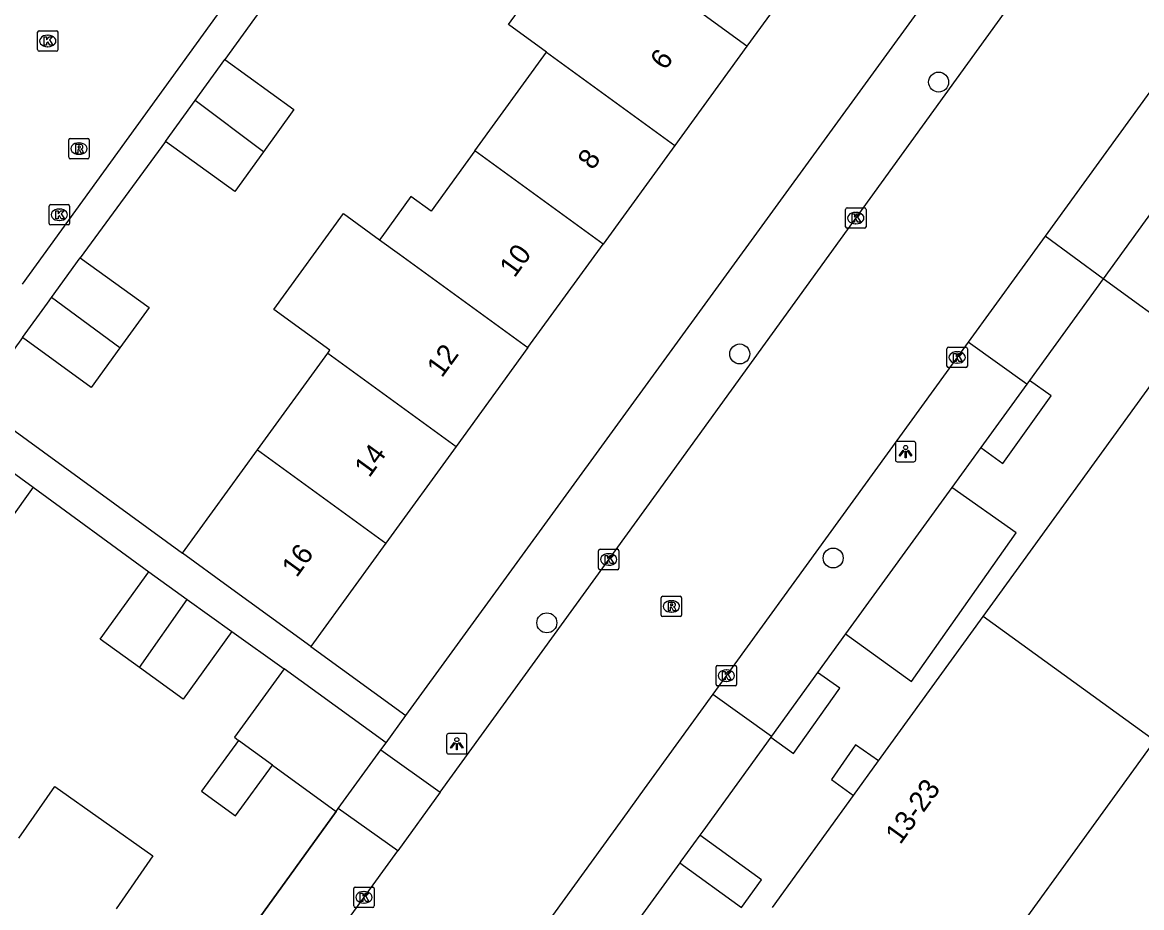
# Model space of a CAD drawing. Extents: x 159675 to 160530, y 382179 to 382901.
# Drawn here: x 160284.3 to 160339.1, y 382619.4 to 382662.7 of the extents above; entities that cross this region are included whole.
import ezdxf

# ---------------------------------------------------------------- set-up
doc = ezdxf.new("R2010")
doc.units = 0
for name, color, linetype in [('IMGEO_Boom', 7, 'Continuous'), ('IMGEO_Kolk', 7, 'Continuous'), ('IMGEO_Lichtpunt', 7, 'Continuous'), ('IMGEO_Muur', 7, 'Continuous'), ('IMGEO_Pand', 7, 'Continuous'), ('IMGEO_Pand_nummerreeks', 7, 'Continuous'), ('IMGEO_Rijbaan_lokaal_gesloten', 7, 'Continuous'), ('IMGEO_Rijbaan_lokaal_open', 7, 'Continuous'), ('IMGEO_Rioolput', 7, 'Continuous'), ('IMGEO_Voetpad_open', 7, 'Continuous')]:
    doc.layers.add(name, color=color, linetype=linetype)

msp = doc.modelspace()

# ---------------------------------------------------------------- linework, layer by layer
at = {"layer": 'IMGEO_Boom'}
for centre in [(160329.135, 382659.771), (160319.394, 382646.462), (160323.969, 382636.475), (160309.945, 382633.301)]:
    msp.add_circle(centre, 0.489, dxfattribs=at)
at = {"layer": 'IMGEO_Kolk'}
for p, q in [((160284.999, 382661.358), (160284.999, 382662.21)), ((160285.074, 382662.284), (160285.926, 382662.284)), ((160285.487, 382662.064), (160285.512, 382662.064)), ((160286, 382662.21), (160286, 382661.358)), ((160285.51, 382661.504), (160285.485, 382661.504)), ((160285.926, 382661.284), (160285.074, 382661.284)), ((160285.567, 382652.85), (160285.567, 382653.702)), ((160285.642, 382653.776), (160286.494, 382653.776)), ((160286.568, 382653.702), (160286.568, 382652.85)), ((160286.055, 382653.556), (160286.08, 382653.556)), ((160324.577, 382652.689), (160324.577, 382653.541)), ((160324.652, 382653.615), (160325.504, 382653.615)), ((160325.065, 382653.395), (160325.09, 382653.395)), ((160325.578, 382653.541), (160325.578, 382652.689)), ((160286.494, 382652.776), (160285.642, 382652.776)), ((160286.078, 382652.996), (160286.053, 382652.996)), ((160325.504, 382652.615), (160324.652, 382652.615)), ((160325.088, 382652.835), (160325.063, 382652.835)), ((160329.543, 382645.867), (160329.543, 382646.719)), ((160329.618, 382646.793), (160330.47, 382646.793)), ((160330.031, 382646.573), (160330.056, 382646.573)), ((160330.544, 382646.719), (160330.544, 382645.867)), ((160330.47, 382645.793), (160329.618, 382645.793)), ((160330.054, 382646.013), (160330.029, 382646.013)), ((160312.475, 382635.977), (160312.475, 382636.829)), ((160312.55, 382636.903), (160313.402, 382636.903)), ((160313.476, 382636.829), (160313.476, 382635.977)), ((160312.963, 382636.683), (160312.988, 382636.683)), ((160313.402, 382635.903), (160312.55, 382635.903)), ((160312.986, 382636.123), (160312.961, 382636.123)), ((160318.311, 382631.216), (160319.163, 382631.216)), ((160318.236, 382630.29), (160318.236, 382631.142)), ((160318.724, 382630.996), (160318.749, 382630.996)), ((160319.237, 382631.142), (160319.237, 382630.29)), ((160319.163, 382630.216), (160318.311, 382630.216)), ((160318.747, 382630.436), (160318.722, 382630.436)), ((160300.487, 382619.441), (160300.487, 382620.293)), ((160300.562, 382620.367), (160301.414, 382620.367)), ((160301.488, 382620.293), (160301.488, 382619.441)), ((160300.975, 382620.147), (160301, 382620.147)), ((160301.414, 382619.367), (160300.562, 382619.367)), ((160300.998, 382619.587), (160300.973, 382619.587))]:
    msp.add_line(p, q, dxfattribs=at)
for points in [[(160284.999, 382661.358), (160284.999, 382662.21)], [(160285.074, 382662.284), (160285.926, 382662.284)], [(160285.32, 382661.984), (160285.443, 382661.984), (160285.443, 382661.833), (160285.573, 382661.984), (160285.737, 382661.984), (160285.591, 382661.833), (160285.744, 382661.584), (160285.592, 382661.584), (160285.507, 382661.748), (160285.443, 382661.681), (160285.443, 382661.584), (160285.32, 382661.584), (160285.32, 382661.984)], [(160286, 382662.21), (160286, 382661.358)], [(160285.926, 382661.284), (160285.074, 382661.284)], [(160285.567, 382652.85), (160285.567, 382653.702)], [(160285.642, 382653.776), (160286.494, 382653.776)], [(160286.568, 382653.702), (160286.568, 382652.85)], [(160285.888, 382653.476), (160286.011, 382653.476), (160286.011, 382653.325), (160286.141, 382653.476), (160286.305, 382653.476), (160286.159, 382653.325), (160286.312, 382653.076), (160286.16, 382653.076), (160286.075, 382653.24), (160286.011, 382653.173), (160286.011, 382653.076), (160285.888, 382653.076), (160285.888, 382653.476)], [(160324.577, 382652.689), (160324.577, 382653.541)], [(160324.652, 382653.615), (160325.504, 382653.615)], [(160324.898, 382653.315), (160325.021, 382653.315), (160325.021, 382653.164), (160325.151, 382653.315), (160325.315, 382653.315), (160325.169, 382653.164), (160325.322, 382652.915), (160325.17, 382652.915), (160325.085, 382653.079), (160325.021, 382653.012), (160325.021, 382652.915), (160324.898, 382652.915), (160324.898, 382653.315)], [(160325.578, 382653.541), (160325.578, 382652.689)], [(160286.494, 382652.776), (160285.642, 382652.776)], [(160325.504, 382652.615), (160324.652, 382652.615)], [(160329.543, 382645.867), (160329.543, 382646.719)], [(160329.618, 382646.793), (160330.47, 382646.793)], [(160330.544, 382646.719), (160330.544, 382645.867)], [(160329.864, 382646.493), (160329.987, 382646.493), (160329.987, 382646.342), (160330.117, 382646.493), (160330.281, 382646.493), (160330.135, 382646.342), (160330.288, 382646.093), (160330.136, 382646.093), (160330.051, 382646.257), (160329.987, 382646.19), (160329.987, 382646.093), (160329.864, 382646.093), (160329.864, 382646.493)], [(160330.47, 382645.793), (160329.618, 382645.793)], [(160312.475, 382635.977), (160312.475, 382636.829)], [(160312.55, 382636.903), (160313.402, 382636.903)], [(160313.476, 382636.829), (160313.476, 382635.977)], [(160312.796, 382636.603), (160312.919, 382636.603), (160312.919, 382636.452), (160313.049, 382636.603), (160313.213, 382636.603), (160313.067, 382636.452), (160313.22, 382636.203), (160313.068, 382636.203), (160312.983, 382636.367), (160312.919, 382636.3), (160312.919, 382636.203), (160312.796, 382636.203), (160312.796, 382636.603)], [(160313.402, 382635.903), (160312.55, 382635.903)], [(160318.311, 382631.216), (160319.163, 382631.216)], [(160318.236, 382630.29), (160318.236, 382631.142)], [(160318.557, 382630.916), (160318.68, 382630.916), (160318.68, 382630.765), (160318.81, 382630.916), (160318.974, 382630.916), (160318.828, 382630.765), (160318.981, 382630.516), (160318.829, 382630.516), (160318.744, 382630.68), (160318.68, 382630.613), (160318.68, 382630.516), (160318.557, 382630.516), (160318.557, 382630.916)], [(160319.237, 382631.142), (160319.237, 382630.29)], [(160319.163, 382630.216), (160318.311, 382630.216)], [(160300.487, 382619.441), (160300.487, 382620.293)], [(160300.562, 382620.367), (160301.414, 382620.367)], [(160301.488, 382620.293), (160301.488, 382619.441)], [(160300.808, 382620.067), (160300.931, 382620.067), (160300.931, 382619.916), (160301.061, 382620.067), (160301.225, 382620.067), (160301.079, 382619.916), (160301.232, 382619.667), (160301.08, 382619.667), (160300.995, 382619.831), (160300.931, 382619.764), (160300.931, 382619.667), (160300.808, 382619.667), (160300.808, 382620.067)], [(160301.414, 382619.367), (160300.562, 382619.367)]]:
    msp.add_lwpolyline(points, dxfattribs=at)
for centre, start, end in [((160285.076, 382662.208), 91.552, 178.448), ((160285.076, 382662.208), 91.552, 178.448), ((160285.924, 382662.208), 1.552, 88.448), ((160285.924, 382662.208), 1.552, 88.448), ((160285.076, 382661.36), 181.552, 268.448), ((160285.076, 382661.36), 181.552, 268.448), ((160285.924, 382661.36), 271.552, 358.448), ((160285.924, 382661.36), 271.552, 358.448), ((160285.644, 382653.7), 91.552, 178.448), ((160285.644, 382653.7), 91.552, 178.448), ((160286.492, 382653.7), 1.552, 88.448), ((160286.492, 382653.7), 1.552, 88.448), ((160324.654, 382653.539), 91.552, 178.448), ((160324.654, 382653.539), 91.552, 178.448), ((160325.502, 382653.539), 1.552, 88.448), ((160325.502, 382653.539), 1.552, 88.448), ((160285.644, 382652.852), 181.552, 268.448), ((160285.644, 382652.852), 181.552, 268.448), ((160286.492, 382652.852), 271.552, 358.448), ((160286.492, 382652.852), 271.552, 358.448), ((160324.654, 382652.691), 181.552, 268.448), ((160324.654, 382652.691), 181.552, 268.448), ((160325.502, 382652.691), 271.552, 358.448), ((160325.502, 382652.691), 271.552, 358.448), ((160329.62, 382646.717), 91.552, 178.448), ((160329.62, 382646.717), 91.552, 178.448), ((160330.468, 382646.717), 1.552, 88.448), ((160330.468, 382646.717), 1.552, 88.448), ((160329.62, 382645.869), 181.552, 268.448), ((160329.62, 382645.869), 181.552, 268.448), ((160330.468, 382645.869), 271.552, 358.448), ((160330.468, 382645.869), 271.552, 358.448), ((160312.552, 382636.827), 91.552, 178.448), ((160312.552, 382636.827), 91.552, 178.448), ((160313.4, 382636.827), 1.552, 88.448), ((160313.4, 382636.827), 1.552, 88.448), ((160312.552, 382635.979), 181.552, 268.448), ((160312.552, 382635.979), 181.552, 268.448), ((160313.4, 382635.979), 271.552, 358.448), ((160313.4, 382635.979), 271.552, 358.448), ((160318.313, 382631.14), 91.552, 178.448), ((160318.313, 382631.14), 91.552, 178.448), ((160319.161, 382631.14), 1.552, 88.448), ((160319.161, 382631.14), 1.552, 88.448), ((160318.313, 382630.292), 181.552, 268.448), ((160318.313, 382630.292), 181.552, 268.448), ((160319.161, 382630.292), 271.552, 358.448), ((160319.161, 382630.292), 271.552, 358.448), ((160300.564, 382620.291), 91.552, 178.448), ((160300.564, 382620.291), 91.552, 178.448), ((160301.412, 382620.291), 1.552, 88.448), ((160301.412, 382620.291), 1.552, 88.448), ((160300.564, 382619.443), 181.552, 268.448), ((160300.564, 382619.443), 181.552, 268.448), ((160301.412, 382619.443), 271.552, 358.448), ((160301.412, 382619.443), 271.552, 358.448)]:
    msp.add_arc(centre, 0.0765, start, end, dxfattribs=at)
for centre, major_axis, ratio, start_param, end_param in [((160285.486, 382661.784), (-0.387, 0.002), 0.722429, 4.712389, 7.853982), ((160285.511, 382661.784), (-0.39, 0.002), 0.717154, 1.570796, 4.712389), ((160286.054, 382653.276), (-0.387, 0.002), 0.722429, 4.712389, 7.853982), ((160286.079, 382653.276), (-0.39, 0.002), 0.717154, 1.570796, 4.712389), ((160325.064, 382653.115), (-0.387, 0.002), 0.722429, 4.712389, 7.853982), ((160325.089, 382653.115), (-0.39, 0.002), 0.717154, 1.570796, 4.712389), ((160330.03, 382646.293), (-0.387, 0.002), 0.722429, 4.712389, 7.853982), ((160330.055, 382646.293), (-0.39, 0.002), 0.717154, 1.570796, 4.712389), ((160312.962, 382636.403), (-0.387, 0.002), 0.722429, 4.712389, 7.853982), ((160312.987, 382636.403), (-0.39, 0.002), 0.717154, 1.570796, 4.712389), ((160318.723, 382630.716), (-0.387, 0.002), 0.722429, 4.712389, 7.853982), ((160318.748, 382630.716), (-0.39, 0.002), 0.717154, 1.570796, 4.712389), ((160300.974, 382619.867), (-0.387, 0.002), 0.722429, 4.712389, 7.853982), ((160300.999, 382619.867), (-0.39, 0.002), 0.717154, 1.570796, 4.712389)]:
    msp.add_ellipse(centre, major_axis=major_axis, ratio=ratio, start_param=start_param, end_param=end_param, dxfattribs=at)
at = {"layer": 'IMGEO_Lichtpunt'}
for p, q in [((160327.92, 382642.181), (160327.112, 382642.181)), ((160327.92, 382642.181), (160327.112, 382642.181)), ((160327.018, 382642.086), (160327.018, 382641.279)), ((160327.018, 382642.086), (160327.018, 382641.279)), ((160328.014, 382641.279), (160328.014, 382642.086)), ((160328.014, 382641.279), (160328.014, 382642.086)), ((160327.112, 382641.185), (160327.92, 382641.185)), ((160327.112, 382641.185), (160327.92, 382641.185)), ((160305.037, 382627.787), (160305.037, 382626.98)), ((160305.037, 382627.787), (160305.037, 382626.98)), ((160305.939, 382627.882), (160305.131, 382627.882)), ((160305.939, 382627.882), (160305.131, 382627.882)), ((160306.033, 382626.98), (160306.033, 382627.787)), ((160306.033, 382626.98), (160306.033, 382627.787)), ((160305.131, 382626.886), (160305.939, 382626.886)), ((160305.131, 382626.886), (160305.939, 382626.886))]:
    msp.add_line(p, q, dxfattribs=at)
for points in [[(160327.392, 382641.75), (160327.431, 382641.722), (160327.243, 382641.46), (160327.205, 382641.487), (160327.392, 382641.75)], [(160327.494, 382641.702), (160327.541, 382641.702), (160327.541, 382641.38), (160327.494, 382641.38), (160327.494, 382641.702)], [(160327.604, 382641.722), (160327.642, 382641.749), (160327.829, 382641.487), (160327.79, 382641.459), (160327.604, 382641.722)], [(160305.411, 382627.451), (160305.45, 382627.423), (160305.262, 382627.161), (160305.224, 382627.188), (160305.411, 382627.451)], [(160305.513, 382627.403), (160305.56, 382627.403), (160305.56, 382627.081), (160305.513, 382627.081), (160305.513, 382627.403)], [(160305.623, 382627.423), (160305.661, 382627.45), (160305.848, 382627.188), (160305.809, 382627.16), (160305.623, 382627.423)]]:
    msp.add_lwpolyline(points, dxfattribs=at)
for centre in [(160327.517, 382641.884), (160305.536, 382627.585)]:
    msp.add_circle(centre, 0.0994, dxfattribs=at)
for centre, start, end in [((160327.112, 382642.086), 90, 180), ((160327.112, 382642.086), 90, 180), ((160327.92, 382642.086), 0, 90), ((160327.92, 382642.086), 0, 90), ((160327.112, 382641.279), 180, 270), ((160327.112, 382641.279), 180, 270), ((160327.92, 382641.279), 270, 0), ((160327.92, 382641.279), 270, 360), ((160305.131, 382627.787), 90, 180), ((160305.131, 382627.787), 90, 180), ((160305.939, 382627.787), 0, 90), ((160305.939, 382627.787), 0, 90), ((160305.131, 382626.98), 180, 270), ((160305.131, 382626.98), 180, 270), ((160305.939, 382626.98), 270, 0), ((160305.939, 382626.98), 270, 360)]:
    msp.add_arc(centre, 0.0946, start, end, dxfattribs=at)
at = {"layer": 'IMGEO_Muur'}
msp.add_lwpolyline([(160293.648, 382615.802), (160299.627, 382624.071)], dxfattribs=at)
at = {"layer": 'IMGEO_Pand'}
for points in [[(160309.935, 382661.236), (160308.069, 382662.592), (160311.603, 382667.452), (160313.468, 382666.096)], [(160323.294, 382666.411), (160319.746, 382661.531)], [(160319.746, 382661.531), (160313.468, 382666.096)], [(160319.746, 382661.531), (160316.213, 382656.672)], [(160292.711, 382658.862), (160294.169, 382660.875)], [(160294.169, 382660.875), (160297.557, 382658.421), (160296.058, 382656.351)], [(160306.42, 382656.402), (160309.935, 382661.236)], [(160309.935, 382661.236), (160316.213, 382656.672)], [(160291.267, 382656.868), (160292.711, 382658.862)], [(160296.058, 382656.351), (160292.711, 382658.862)], [(160296.058, 382656.351), (160294.655, 382654.414), (160291.267, 382656.868)], [(160316.213, 382656.672), (160312.699, 382651.838)], [(160306.42, 382656.402), (160304.274, 382653.45), (160303.289, 382654.166), (160301.856, 382652.195), (160301.754, 382652.054)], [(160312.699, 382651.838), (160306.42, 382656.402)], [(160299.211, 382646.501), (160299.316, 382646.646), (160296.571, 382648.642), (160299.987, 382653.339), (160301.754, 382652.054)], [(160301.754, 382652.054), (160302.732, 382651.343), (160309.017, 382646.774)], [(160309.017, 382646.774), (160312.699, 382651.838)], [(160285.682, 382649.223), (160287.092, 382651.169)], [(160287.092, 382651.169), (160290.458, 382648.73), (160289.028, 382646.756)], [(160284.261, 382647.261), (160285.478, 382648.941), (160285.682, 382649.223)], [(160289.028, 382646.756), (160285.682, 382649.223)], [(160289.028, 382646.756), (160287.627, 382644.822), (160284.261, 382647.261)], [(160331.322, 382633.61), (160341.198, 382647.23)], [(160309.017, 382646.774), (160305.496, 382641.932)], [(160295.778, 382641.778), (160299.211, 382646.501)], [(160299.211, 382646.501), (160305.496, 382641.932)], [(160292.097, 382636.716), (160295.778, 382641.778)], [(160295.778, 382641.778), (160302.062, 382637.209)], [(160305.496, 382641.932), (160302.062, 382637.209)], [(160282.782, 382641.394), (160284.791, 382639.949)], [(160284.791, 382639.949), (160282.418, 382636.648), (160280.388, 382638.107)], [(160298.382, 382632.147), (160294.337, 382635.087), (160292.097, 382636.716)], [(160302.062, 382637.209), (160298.382, 382632.147)], [(160289.984, 382631.118), (160288.07, 382632.495), (160290.443, 382635.796)], [(160290.443, 382635.796), (160292.329, 382634.44)], [(160289.984, 382631.118), (160292.329, 382634.44)], [(160292.329, 382634.44), (160294.51, 382632.872)], [(160326.195, 382626.539), (160331.322, 382633.61)], [(160339.718, 382627.522), (160331.322, 382633.61)], [(160294.51, 382632.872), (160292.137, 382629.571), (160289.984, 382631.118)], [(160297.081, 382631.057), (160294.639, 382627.698), (160294.847, 382627.547)], [(160302.069, 382627.43), (160297.081, 382631.057)], [(160294.847, 382627.547), (160293.034, 382625.054), (160294.691, 382623.849), (160296.504, 382626.342)], [(160296.504, 382626.342), (160294.847, 382627.547)], [(160301.82, 382627.087), (160302.069, 382627.43)], [(160329.387, 382613.273), (160339.718, 382627.522)], [(160299.725, 382624.206), (160301.82, 382627.087)], [(160296.504, 382626.342), (160299.627, 382624.071)], [(160324.966, 382624.844), (160326.195, 382626.539)], [(160284.088, 382622.763), (160285.838, 382625.288), (160290.642, 382621.897), (160288.85, 382619.295)], [(160320.991, 382619.361), (160324.966, 382624.844)], [(160299.627, 382624.071), (160299.725, 382624.206)]]:
    msp.add_lwpolyline(points, dxfattribs=at)
at = {"layer": 'IMGEO_Rijbaan_lokaal_gesloten'}
for points in [[(160304.717, 382625.008), (160315.311, 382639.622), (160336.801, 382669.305)], [(160339.953, 382659.947), (160334.351, 382652.23)], [(160334.351, 382652.23), (160330.581, 382647.035)], [(160330.581, 382647.035), (160318.081, 382629.815)], [(160318.081, 382629.815), (160314.718, 382625.182), (160313.661, 382623.726), (160310.216, 382618.98)], [(160304.717, 382625.008), (160302.639, 382622.143)], [(160290.62, 382605.563), (160302.639, 382622.143)]]:
    msp.add_lwpolyline(points, dxfattribs=at)
at = {"layer": 'IMGEO_Rijbaan_lokaal_open'}
msp.add_lwpolyline([(160313.249, 382689.912), (160284.25, 382649.875)], dxfattribs=at)
at = {"layer": 'IMGEO_Rioolput'}
for p, q in [((160286.602, 382657.015), (160287.454, 382657.015)), ((160286.527, 382656.089), (160286.527, 382656.941)), ((160287.015, 382656.795), (160287.04, 382656.795)), ((160287.528, 382656.941), (160287.528, 382656.089)), ((160287.454, 382656.015), (160286.602, 382656.015)), ((160287.038, 382656.235), (160287.013, 382656.235)), ((160315.546, 382633.678), (160315.546, 382634.53)), ((160315.621, 382634.604), (160316.473, 382634.604)), ((160316.547, 382634.53), (160316.547, 382633.678)), ((160316.034, 382634.384), (160316.059, 382634.384)), ((160316.473, 382633.604), (160315.621, 382633.604)), ((160316.057, 382633.824), (160316.032, 382633.824))]:
    msp.add_line(p, q, dxfattribs=at)
for points in [[(160286.602, 382657.015), (160287.454, 382657.015)], [(160286.527, 382656.089), (160286.527, 382656.941)], [(160287.116, 382656.713), (160286.864, 382656.715), (160286.864, 382656.315)], [(160286.864, 382656.315), (160286.988, 382656.315), (160286.988, 382656.477), (160286.999, 382656.477)], [(160287.042, 382656.634), (160286.988, 382656.634), (160286.988, 382656.553)], [(160286.988, 382656.553), (160287.04, 382656.553)], [(160287.046, 382656.448), (160287.117, 382656.315), (160287.257, 382656.315), (160287.192, 382656.441)], [(160287.528, 382656.941), (160287.528, 382656.089)], [(160287.454, 382656.015), (160286.602, 382656.015)], [(160315.546, 382633.678), (160315.546, 382634.53)], [(160315.621, 382634.604), (160316.473, 382634.604)], [(160316.547, 382634.53), (160316.547, 382633.678)], [(160316.135, 382634.302), (160315.883, 382634.304), (160315.883, 382633.904)], [(160315.883, 382633.904), (160316.007, 382633.904), (160316.007, 382634.066), (160316.018, 382634.066)], [(160316.061, 382634.223), (160316.007, 382634.223), (160316.007, 382634.142)], [(160316.007, 382634.142), (160316.059, 382634.142)], [(160316.065, 382634.037), (160316.136, 382633.904), (160316.276, 382633.904), (160316.211, 382634.03)], [(160316.473, 382633.604), (160315.621, 382633.604)]]:
    msp.add_lwpolyline(points, dxfattribs=at)
for centre, radius, start, end in [((160286.604, 382656.939), 0.0765, 91.552, 178.448), ((160286.604, 382656.939), 0.0765, 91.552, 178.448), ((160287.452, 382656.939), 0.0765, 1.552, 88.448), ((160287.452, 382656.939), 0.0765, 1.552, 88.448), ((160286.998, 382656.424), 0.0533, 26.0293, 88.6989), ((160287.024, 382656.742), 0.19, 274.7715, 282.9687), ((160287.048, 382656.538), 0.0964, 77.0061, 93.1865), ((160287.062, 382656.595), 0.0378, 276.6634, 79.6772), ((160287.115, 382656.603), 0.109, 350.3612, 89.416), ((160287.113, 382656.603), 0.112, 277.5842, 350.9817), ((160287.097, 382656.388), 0.108, 29.5134, 73.7905), ((160286.604, 382656.091), 0.0765, 181.552, 268.448), ((160286.604, 382656.091), 0.0765, 181.552, 268.448), ((160287.452, 382656.091), 0.0765, 271.552, 358.448), ((160287.452, 382656.091), 0.0765, 271.552, 358.448), ((160315.623, 382634.528), 0.0765, 91.552, 178.448), ((160315.623, 382634.528), 0.0765, 91.552, 178.448), ((160316.471, 382634.528), 0.0765, 1.552, 88.448), ((160316.471, 382634.528), 0.0765, 1.552, 88.448), ((160316.017, 382634.013), 0.0533, 26.0293, 88.6989), ((160316.043, 382634.331), 0.19, 274.7715, 282.9687), ((160316.067, 382634.127), 0.0964, 77.0061, 93.1865), ((160316.081, 382634.184), 0.0378, 276.6634, 79.6772), ((160316.134, 382634.192), 0.109, 350.3612, 89.416), ((160316.132, 382634.192), 0.112, 277.5842, 350.9817), ((160316.116, 382633.977), 0.108, 29.5134, 73.7905), ((160315.623, 382633.68), 0.0765, 181.552, 268.448), ((160315.623, 382633.68), 0.0765, 181.552, 268.448), ((160316.471, 382633.68), 0.0765, 271.552, 358.448), ((160316.471, 382633.68), 0.0765, 271.552, 358.448)]:
    msp.add_arc(centre, radius, start, end, dxfattribs=at)
for centre, major_axis, ratio, start_param, end_param in [((160287.014, 382656.515), (-0.387, 0.002), 0.722429, 4.712389, 7.853982), ((160287.039, 382656.515), (-0.39, 0.002), 0.717154, 1.570796, 4.712389), ((160316.033, 382634.104), (-0.387, 0.002), 0.722429, 4.712389, 7.853982), ((160316.058, 382634.104), (-0.39, 0.002), 0.717154, 1.570796, 4.712389)]:
    msp.add_ellipse(centre, major_axis=major_axis, ratio=ratio, start_param=start_param, end_param=end_param, dxfattribs=at)
at = {"layer": 'IMGEO_Voetpad_open'}
for points in [[(160303.037, 382628.76), (160333.537, 382670.671)], [(160298.315, 382666.628), (160294.169, 382660.875)], [(160342.684, 382657.705), (160337.191, 382650.136)], [(160291.267, 382656.868), (160287.092, 382651.169)], [(160337.191, 382650.136), (160334.351, 382652.23)], [(160337.191, 382650.136), (160333.585, 382645.167)], [(160341.198, 382647.23), (160337.191, 382650.136)], [(160284.261, 382647.261), (160281.962, 382644.087), (160292.097, 382636.716)], [(160333.454, 382644.987), (160330.581, 382647.035)], [(160331.201, 382641.882), (160332.287, 382641.094), (160334.644, 382644.416), (160333.585, 382645.167)], [(160333.454, 382644.987), (160331.201, 382641.882)], [(160333.585, 382645.167), (160333.454, 382644.987)], [(160331.201, 382641.882), (160329.782, 382639.927)], [(160284.791, 382639.949), (160290.443, 382635.796)], [(160329.782, 382639.927), (160324.581, 382632.761)], [(160324.581, 382632.761), (160327.8, 382630.425), (160332.932, 382637.706), (160329.782, 382639.927)], [(160294.51, 382632.872), (160297.081, 382631.057)], [(160324.581, 382632.761), (160323.207, 382630.867)], [(160298.382, 382632.147), (160303.037, 382628.76)], [(160320.916, 382627.71), (160322.034, 382626.899), (160324.295, 382630.099), (160323.207, 382630.867)], [(160323.207, 382630.867), (160320.946, 382627.751)], [(160318.081, 382629.815), (160320.946, 382627.751)], [(160302.069, 382627.43), (160303.037, 382628.76)], [(160320.916, 382627.71), (160317.578, 382623.11), (160317.434, 382622.912)], [(160320.946, 382627.751), (160320.916, 382627.71)], [(160301.82, 382627.087), (160304.717, 382625.008)], [(160326.195, 382626.539), (160325.056, 382627.328), (160323.88, 382625.632), (160324.966, 382624.844)], [(160302.639, 382622.143), (160299.725, 382624.206)], [(160299.627, 382624.071), (160293.648, 382615.802)], [(160317.434, 382622.912), (160316.505, 382621.632), (160316.452, 382621.559)], [(160316.452, 382621.559), (160319.476, 382619.364), (160320.459, 382620.718), (160317.434, 382622.912)], [(160316.452, 382621.559), (160313.066, 382616.893)]]:
    msp.add_lwpolyline(points, dxfattribs=at)

# ---------------------------------------------------------------- texts
at = {"layer": 'IMGEO_Pand_nummerreeks'}
for s, rotation, p in [('6', 53.9784, (160315.741, 382660.308)), ('8', 53.9812, (160312.188, 382655.421)), ('10', 53.9784, (160308.359, 382650.156)), ('12', 53.9784, (160304.8, 382645.26)), ('14', 53.9812, (160301.246, 382640.37)), ('16', 53.9812, (160297.69, 382635.479)), ('13-23', 54.0528, (160327.254, 382622.411))]:
    msp.add_text(s, height=1, rotation=rotation, dxfattribs=at).set_placement(p)

doc.saveas('drawing.dxf')
